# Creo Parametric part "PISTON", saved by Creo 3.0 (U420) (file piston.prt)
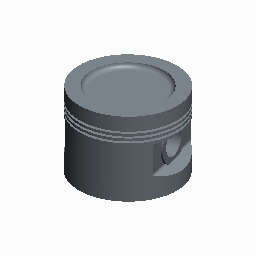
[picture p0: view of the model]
Units: millimeter Kilogram Sec (mmKs); MM, KILOGRAM, SECS

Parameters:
  MATERIAL = "ST37"

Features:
  1. datum plane "RIGHT"
  2. datum plane "TOP"
  3. datum plane "FRONT"
  4. coordinate system
  5. protrusion
  6. cut
  7. round
  8. datum plane "PIN_PLN"
  9. datum axis
  10. curve
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
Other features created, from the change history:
  mirror "Mirror 1"
  extrusion "Extrude 8 (2)"
  extrusion "Extrude 15" (2 times)
  mirror "Mirror 2"
  extrusion "Extrude 8 (3)"
  hole "Hole 1"
  round "Round 2"
  revolved cut "Revolve 3"
  pattern "Pattern 1"
  revolved cut "Revolve 3 [2]"
  revolved cut "Revolve 3 [3]"
  planar section "A" (2 times)
  planar section "B" (2 times)
  planar section "C"
  planar section "D"
  round "Round 3"

Other named items: TOP_CUT, BOTTOM_CUT, PIN_AXIS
